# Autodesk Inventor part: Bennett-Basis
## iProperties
Created: 2004-09
Part Number: Bennett-Basis
Document SubType Name: Modeling
Designer: W. Holzwarth
Manufacturer: Standard
Standards Organization: Custom
Author: W. Holzwarth
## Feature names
1. Extrusion1
2. Extrusion2
3. Extrusion3
4. Extrusion4
5. Extrusion5
6. Extrusion6
7. Fase1 [Chamfer]
8. Rundung2 [Fillet]
